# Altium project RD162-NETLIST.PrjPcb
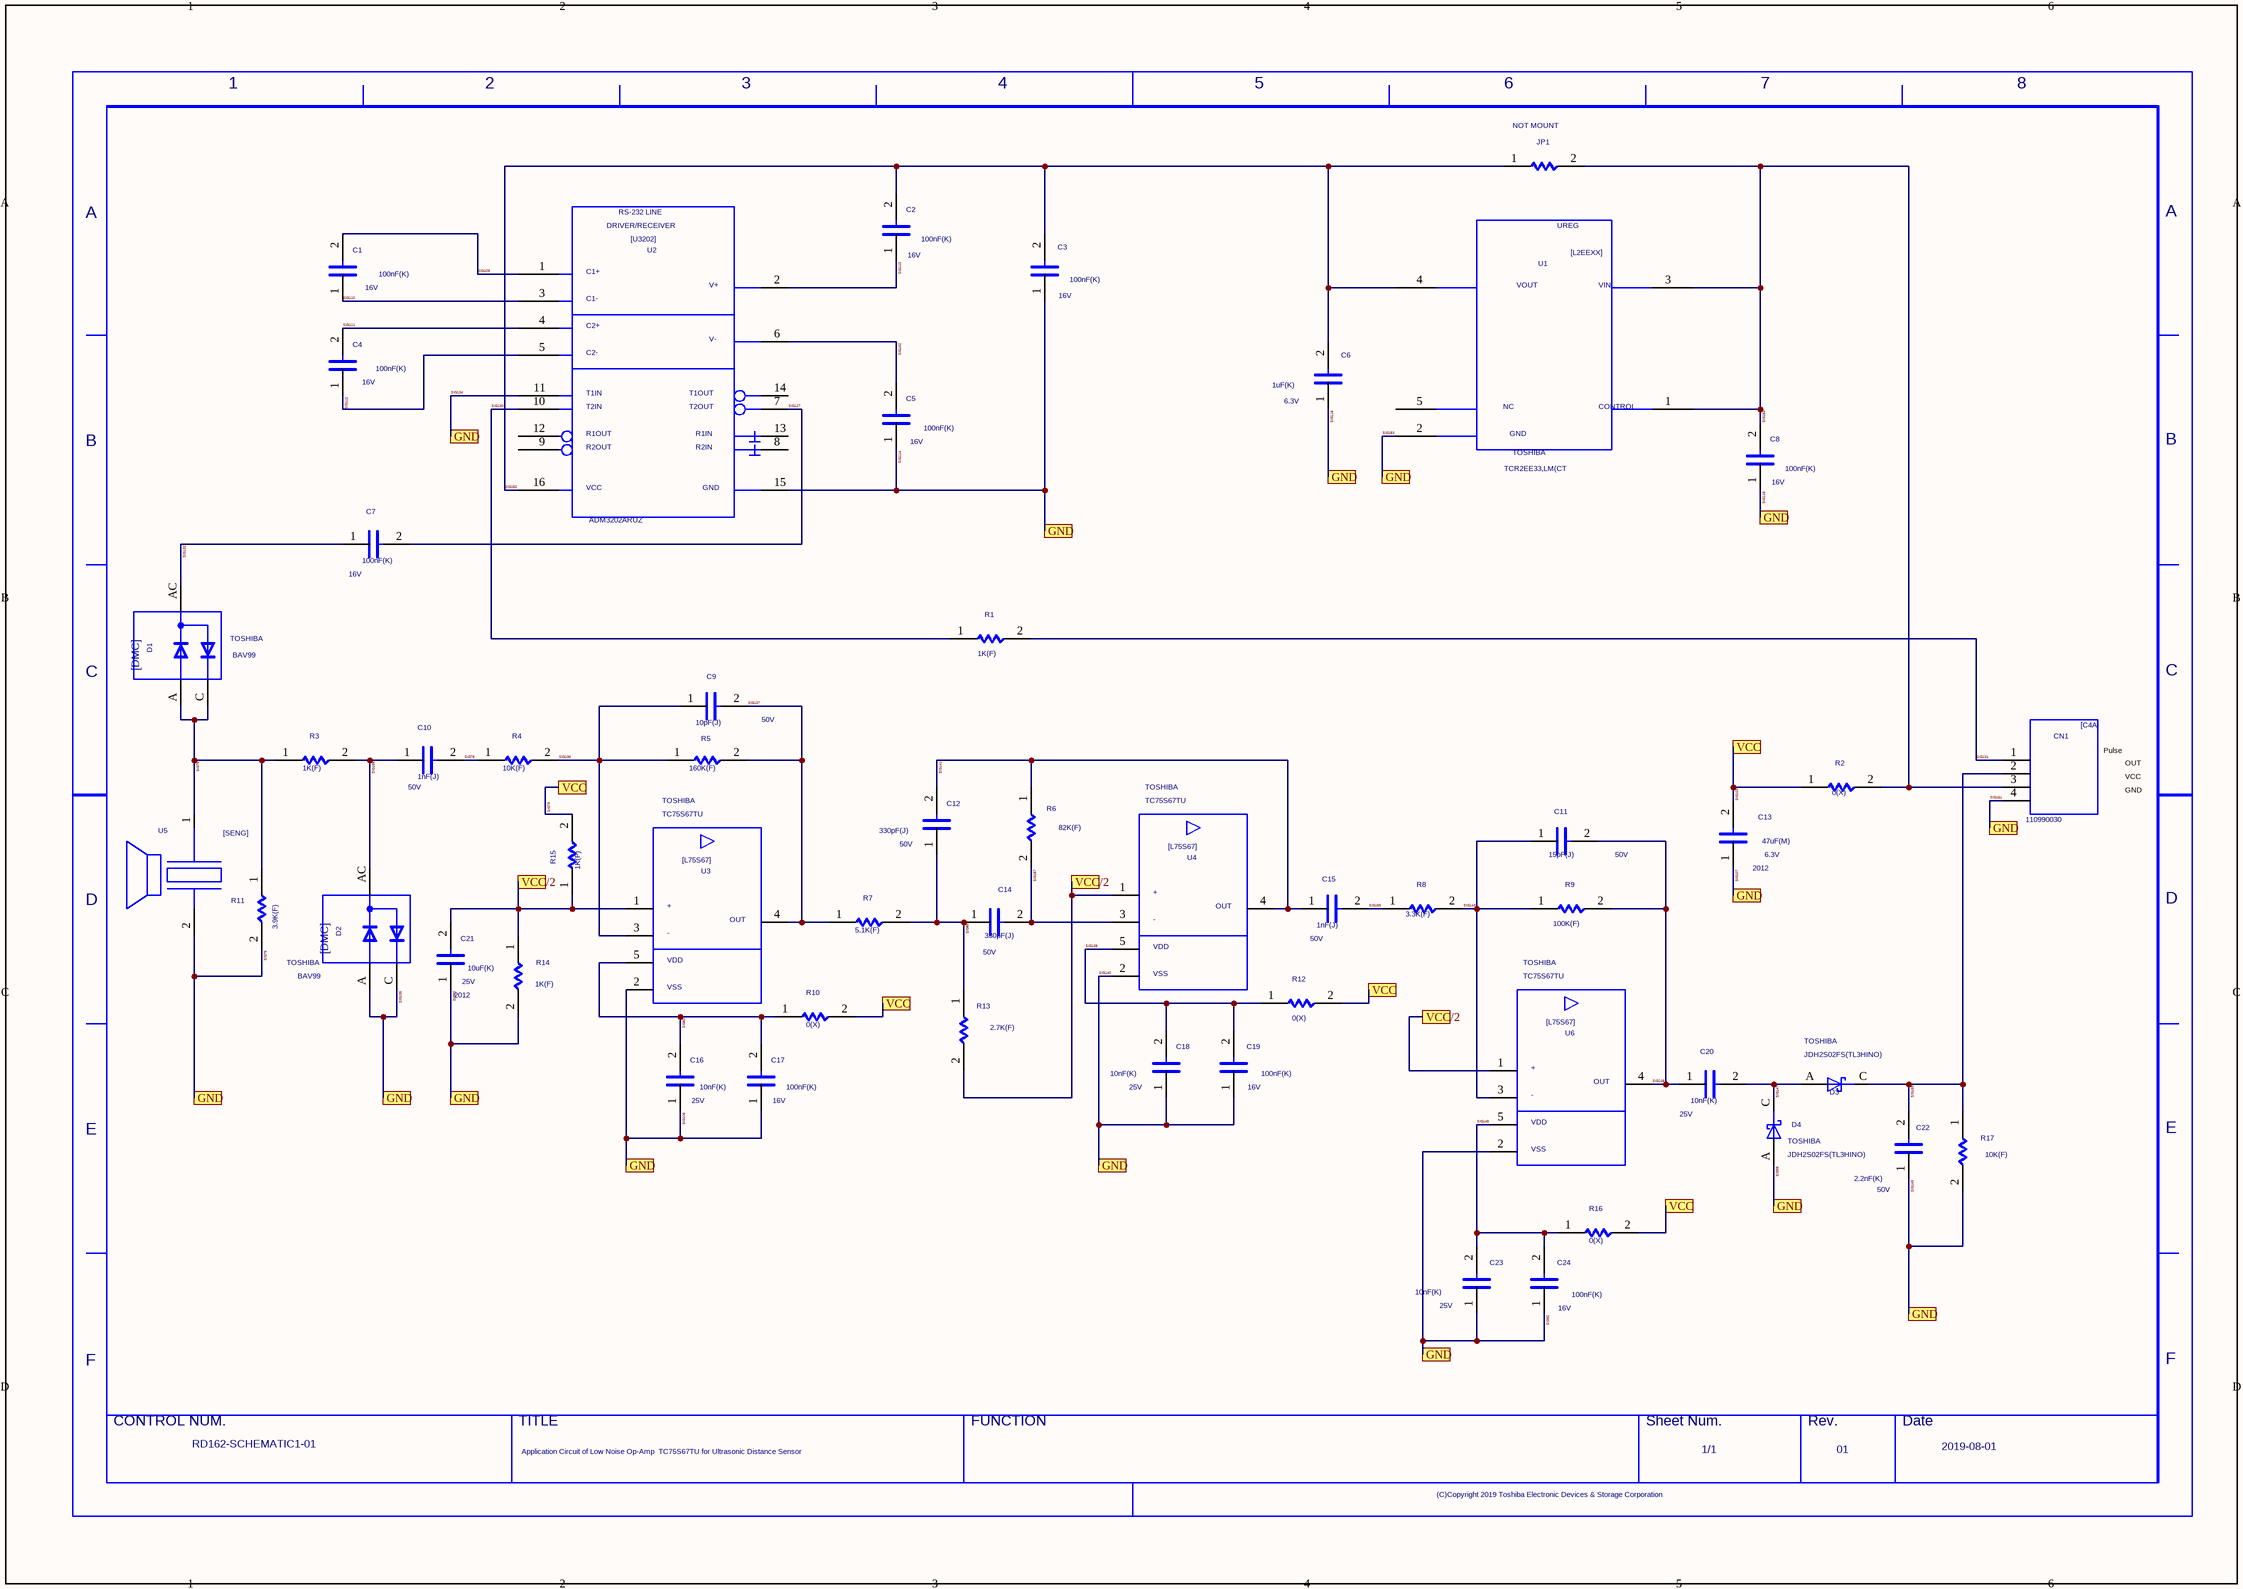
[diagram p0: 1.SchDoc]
1 sheet, 54 parts. Net scope: flat (ports and power ports of the same name join across sheets).

## Sheet 1.SchDoc
size 420 x 297 mm

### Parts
C1  VAL2: 16V  VAL1: 100nF(K)  (hidden comment: C)
C2  VAL2: 16V  VAL1: 100nF(K)  (hidden comment: C)
C3  VAL2: 16V  VAL1: 100nF(K)  (hidden comment: C)
C4  VAL2: 16V  VAL1: 100nF(K)  (hidden comment: C)
C5  VAL2: 16V  VAL1: 100nF(K)  (hidden comment: C)
C6  VAL2: 6.3V  VAL1: 1uF(K)  (hidden comment: C)
C7  VAL2: 16V  VAL1: 100nF(K)  (hidden comment: C)
C8  VAL2: 16V  VAL1: 100nF(K)  (hidden comment: C)
C9  VAL2: 50V  VAL1: 10pF(J)  (hidden comment: C)
C10  VAL2: 50V  VAL1: 1nF(J)  (hidden comment: C)
C11  VAL2: 50V  VAL1: 15pF(J)  (hidden comment: C)
C12  VAL2: 50V  VAL1: 330pF(J)  (hidden comment: C)
C13  SIZECODESMD: 2012  VAL2: 6.3V  VAL1: 47uF(M)  (hidden comment: C)
C14  VAL2: 50V  VAL1: 330pF(J)  (hidden comment: C)
C15  VAL2: 50V  VAL1: 1nF(J)  (hidden comment: C)
C16  VAL2: 25V  VAL1: 10nF(K)  (hidden comment: C)
C17  VAL2: 16V  VAL1: 100nF(K)  (hidden comment: C)
C18  VAL2: 25V  VAL1: 10nF(K)  (hidden comment: C)
C19  VAL2: 16V  VAL1: 100nF(K)  (hidden comment: C)
C20  VAL2: 25V  VAL1: 10nF(K)  (hidden comment: C)
C21  SIZECODESMD: 2012  VAL2: 25V  VAL1: 10uF(K)  (hidden comment: C)
C22  VAL2: 50V  VAL1: 2.2nF(K)  (hidden comment: C)
C23  VAL2: 25V  VAL1: 10nF(K)  (hidden comment: C)
C24  VAL2: 16V  VAL1: 100nF(K)  (hidden comment: C)
CN1  VAL3: 110990030  (hidden comment: C4A)
D1  USERCOMPTEXT3: TOSHIBA  VAL3: BAV99  (hidden comment: DMC)
D2  USERCOMPTEXT3: TOSHIBA  VAL3: BAV99  (hidden comment: DMC)
D3  USERCOMPTEXT3: TOSHIBA  VAL3: JDH2S02FS(TL3HINO)  (hidden comment: SBD)
D4  USERCOMPTEXT3: TOSHIBA  VAL3: JDH2S02FS(TL3HINO)  (hidden comment: SBD)
JP1  NOTMOUNT: NOT MOUNT  (hidden comment: R)
R1  VAL1: 1K(F)  (hidden comment: R)
R2  VAL1: 0(X)  (hidden comment: R)
R3  VAL1: 1K(F)  (hidden comment: R)
R4  VAL1: 10K(F)  (hidden comment: R)
R5  VAL1: 160K(F)  (hidden comment: R)
R6  VAL1: 82K(F)  (hidden comment: R)
R7  VAL1: 5.1K(F)  (hidden comment: R)
R8  VAL1: 3.3K(F)  (hidden comment: R)
R9  VAL1: 100K(F)  (hidden comment: R)
R10  VAL1: 0(X)  (hidden comment: R)
R11  VAL1: 3.9K(F)  (hidden comment: R)
R12  VAL1: 0(X)  (hidden comment: R)
R13  VAL1: 2.7K(F)  (hidden comment: R)
R14  VAL1: 1K(F)  (hidden comment: R)
R15  VAL1: 1K(F)  (hidden comment: R)
R16  VAL1: 0(X)  (hidden comment: R)
R17  VAL1: 10K(F)  (hidden comment: R)
U1  USERCOMPTEXT3: TOSHIBA  VAL3: TCR2EE33,LM(CT  (hidden comment: L2EEXX)
U2  VAL3: ADM3202ARUZ  (hidden comment: U3202)
U3  USERCOMPTEXT3: TOSHIBA  VAL3: TC75S67TU  (hidden comment: L75S67)
U4  USERCOMPTEXT3: TOSHIBA  VAL3: TC75S67TU  (hidden comment: L75S67)
U5  SENG  (value not drawn)
U6  USERCOMPTEXT3: TOSHIBA  VAL3: TC75S67TU  (hidden comment: L75S67)
U?  DATE: 2019-08-01  REVISION: 01  SHEETNUMBER: 1/1  TITLE: Application Circuit of Low Noise Op-Amp / TC75S67TU for Ultrasonic Distance Sensor  DRAWINGNUMBER: RD162-SCHEMATIC1-01  (hidden comment: WAKU_DEF100)

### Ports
GND, VCC, VCC/2

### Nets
SIG76: D1.A D1.C R3.1 R11.1 U5.1
SIG78: C10.2 R4.1
SIG83: C16.2 C17.2 R10.1 U3.5
SIG86: C12.1 C14.1 R7.2 R13.1
SIG103: C13.2 R2.1 R10.2 R12.2 R15.2 R16.2 ; port VCC  [also labelled SIG79]
SIG106: C3.1 C5.1 C6.1 C8.1 C13.1 C16.1 C17.1 C18.1 C19.1 C21.1 C22.1 C23.1 C24.1 CN1.4 D2.A D2.C D4.A R11.2 R14.2 R17.2 U1.2 U2.11 U2.15 U3.2 U4.2 U5.2 U6.2 ; port GND  [also labelled SIG107, SIG114, SIG116, SIG118, SIG134, SIG135, SIG140, SIG149, SIG151, SIG153, SIG75, SIG80, SIG92, SIG99]
SIG109: C1.2 U2.1
SIG110: C1.1 U2.3
SIG111: C4.2 U2.4
SIG112: C4.1 U2.5
SIG113: C2.1 U2.2
SIG127: C7.2 U2.7
SIG130: R1.1 U2.10
SIG131: CN1.1 R1.2
SIG132: C7.1 D1.AC
SIG136: C9.1 R4.2 R5.1 U3.3
SIG137: C9.2 R5.2 R7.1 U3.4
SIG138: C18.2 C19.2 R12.1 U4.5
SIG141: C12.2 C15.1 R6.1 U4.4
SIG143: C11.1 R8.2 R9.1 U6.3
SIG145: C23.2 C24.2 R16.1 U6.5
SIG146: C11.2 C20.1 R9.2 U6.4
SIG147: C20.2 D3.A D4.C
SIG152: C2.2 C3.2 C6.2 JP1.1 U1.4 U2.16
SIG154: C8.2 CN1.3 JP1.2 R2.2 U1.1 U1.3
SIG155: C22.2 CN1.2 D3.C R17.1
SIG156: C10.1 D2.AC R3.2
SIG157: C14.2 R6.2 U4.3
SIG159: C15.2 R8.1
SIG162: C5.2 U2.6
NetC21_2: C21.2 R13.2 R14.1 R15.1 U3.1 U4.1 U6.1 ; port VCC/2

Not connected (* = marked no-connect by the designer): U1 5; U2 8 9 12 13 14

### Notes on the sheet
- Pulse
- OUT
- GND
- VCC

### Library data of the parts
C1-C5 C7 C8 C17 C19 C24 = C: PARTNAME: GDM030002515; OriginalSymbolOrigin: (2540,7620); COMPONENTNAME: GDM030002515_package; MAXGCOUNT: 1; SIZECODESMD: 1005
C6 = C: PARTNAME: GDM030000207; OriginalSymbolOrigin: (2540,7620); COMPONENTNAME: GDM030000207_package; MAXGCOUNT: 1; SIZECODESMD: 1005
C9 = C: PARTNAME: G36030133319; OriginalSymbolOrigin: (2540,7620); MAXGCOUNT: 1; COMPONENTNAME: G36030133319_package; SIZECODESMD: 1005
C10 C15 = C: PARTNAME: GDM030002207; OriginalSymbolOrigin: (2540,7620); MAXGCOUNT: 1; COMPONENTNAME: GDM030002207_package; SIZECODESMD: 1005
C11 = C: PARTNAME: G36030133067; OriginalSymbolOrigin: (2540,7620); MAXGCOUNT: 1; COMPONENTNAME: G36030133067_package; SIZECODESMD: 1005
C12 C14 = C: PARTNAME: GAS030000198; OriginalSymbolOrigin: (2540,7620); MAXGCOUNT: 1; COMPONENTNAME: GAS030000198_package; SIZECODESMD: 1005
C13 = C: PARTNAME: GDM030001363; OriginalSymbolOrigin: (2540,7620); COMPONENTNAME: GDM030001363_package; MAXGCOUNT: 1
C16 C18 C20 C23 = C: PARTNAME: GDM030002441; OriginalSymbolOrigin: (2540,7620); MAXGCOUNT: 1; COMPONENTNAME: GDM030002441_package; SIZECODESMD: 1005
C21 = C: PARTNAME: GDM030002136; OriginalSymbolOrigin: (2540,7620); COMPONENTNAME: GDM030002136_package; MAXGCOUNT: 1
C22 = C: PARTNAME: G36030133234; OriginalSymbolOrigin: (2540,7620); MAXGCOUNT: 1; COMPONENTNAME: G36030133234_package; SIZECODESMD: 1005
CN1 = C4A: PARTNAME: K22S001P; OUMEPARTTYPE: CN; SAVEAREA0: -8845,-265,28754,23475; SAVECOUNT: 22; TIME: 13:28:28; UPDATEUSER: tomizawa-y; UPDATETIME: 15:03:27; OriginalSymbolOrigin: (2540,20320); COMPONENTNAME: K22S001P_package; MAXGCOUNT: 1
D1 D2 = DMC: PARTNAME: K4200526; OUMEPARTTYPE: D; OriginalSymbolOrigin: (5080,20320); COMPONENTNAME: K4200526_package; MAXGCOUNT: 1
D3 D4 = SBD: PARTNAME: GDM420000214; OUMEPARTTYPE: D; SAVEAREA0: -4630,-153,17114,13055; TIME: 14:49:55; UPDATEUSER: fukuda-y; UPDATETIME: 08:16:22; SAVECOUNT: 9; OriginalSymbolOrigin: (5080,5080); COMPONENTNAME: GDM420000214_package; MAXGCOUNT: 1
JP1 = R: PARTNAME: GDM010002886; OriginalSymbolOrigin: (5080,5080); VAL3: ERJ2GE0R00X; VAL2: 63mW; VAL1: 0(X); COMPONENTNAME: GDM010002886_package; MAXGCOUNT: 1; SIZECODESMD: 1005
R1 R3 R14 R15 = R: PARTNAME: GDM010001350; OriginalSymbolOrigin: (5080,5080); COMPONENTNAME: GDM010001350_package; MAXGCOUNT: 1; SIZECODESMD: 1005; VAL2: 100mW
R2 R10 R12 R16 = R: PARTNAME: GDM010002886; OriginalSymbolOrigin: (5080,5080); MAXGCOUNT: 1; COMPONENTNAME: GDM010002886_package; SIZECODESMD: 1005; VAL2: 1A
R4 R17 = R: PARTNAME: GDM010004244; OriginalSymbolOrigin: (5080,5080); MAXGCOUNT: 1; COMPONENTNAME: GDM010004244_package; SIZECODESMD: 1005; VAL2: 100mW
R5 = R: PARTNAME: GDM010001678; OriginalSymbolOrigin: (5080,5080); COMPONENTNAME: GDM010001678_package; MAXGCOUNT: 1; SIZECODESMD: 1005; VAL2: 100mW
R6 = R: PARTNAME: G36010118497; OriginalSymbolOrigin: (5080,5080); MAXGCOUNT: 1; COMPONENTNAME: G36010118497_package; SIZECODESMD: 1005; VAL2: 100mW
R7 = R: PARTNAME: K0100567; OriginalSymbolOrigin: (5080,5080); MAXGCOUNT: 1; COMPONENTNAME: K0100567_package; SIZECODESMD: 1005; VAL2: 100mW
R8 = R: PARTNAME: G36010118343; OriginalSymbolOrigin: (5080,5080); MAXGCOUNT: 1; COMPONENTNAME: G36010118343_package; SIZECODESMD: 1005; VAL2: 100mW
R9 = R: PARTNAME: G36010118060; OriginalSymbolOrigin: (5080,5080); MAXGCOUNT: 1; COMPONENTNAME: G36010118060_package; SIZECODESMD: 1005; VAL2: 100mW
R11 = R: PARTNAME: G36010118633; OriginalSymbolOrigin: (5080,5080); MAXGCOUNT: 1; COMPONENTNAME: G36010118633_package; SIZECODESMD: 1005; VAL2: 100mW
R13 = R: PARTNAME: G36010118619; OriginalSymbolOrigin: (5080,5080); MAXGCOUNT: 1; COMPONENTNAME: G36010118619_package; SIZECODESMD: 1005; VAL2: 100mW
U1 = L2EEXX: PARTNAME: GDM470001887; OUMEPARTTYPE: IC; TIME: 08:44:39; UPDATEUSER: 19990028; UPDATETIME: 08:53:29; SAVECOUNT: 98; SAVEAREA0: -21552,-545,77535,48780; OriginalSymbolOrigin: (7620,45720); COMPONENTNAME: GDM470001887_package; MAXGCOUNT: 1
U2 = U3202: PARTNAME: K47S002D; OUMEPARTTYPE: IC; SAVECOUNT: 55; SAVEAREA0: -25428,-650,76285,64123; TIME: 16:13:33; UPDATEUSER: 19910145; UPDATETIME: 10:59:36; OriginalSymbolOrigin: (7620,60960); COMPONENTNAME: K47S002D_package; MAXGCOUNT: 1
U3 U4 U6 = L75S67: PARTNAME: K47S002A; OUMEPARTTYPE: IC; TIME: 16:27:13; UPDATEUSER: 19990028; UPDATETIME: 13:02:06; SAVECOUNT: 13; SAVEAREA0: -72307,-25685,103712,61936; OriginalSymbolOrigin: (5080,35560); COMPONENTNAME: K47S002A_package; MAXGCOUNT: 1
U5 = SENG: PARTNAME: K30S0001; OUMEPARTTYPE: MT; SAVEAREA0: -37507,-14886,68094,37681; SAVECOUNT: 6; TIME: 16:49:52; UPDATEUSER: w90028dm; UPDATETIME: 08:15:42; OriginalSymbolOrigin: (2540,20320); COMPONENTNAME: K30S0001_package; MAXGCOUNT: 1; VAL3: C4016A1
U? = WAKU_DEF100: PLOTTIME: HH:MM; SAVEAREA0: 198008,-65938,436964,90161; TIME: 14:30:25; UPDATEUSER: cae; UPDATETIME: 16:56:55; SAVECOUNT: 4; OriginalSymbolOrigin: (10160,284480); FUNCTION: None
